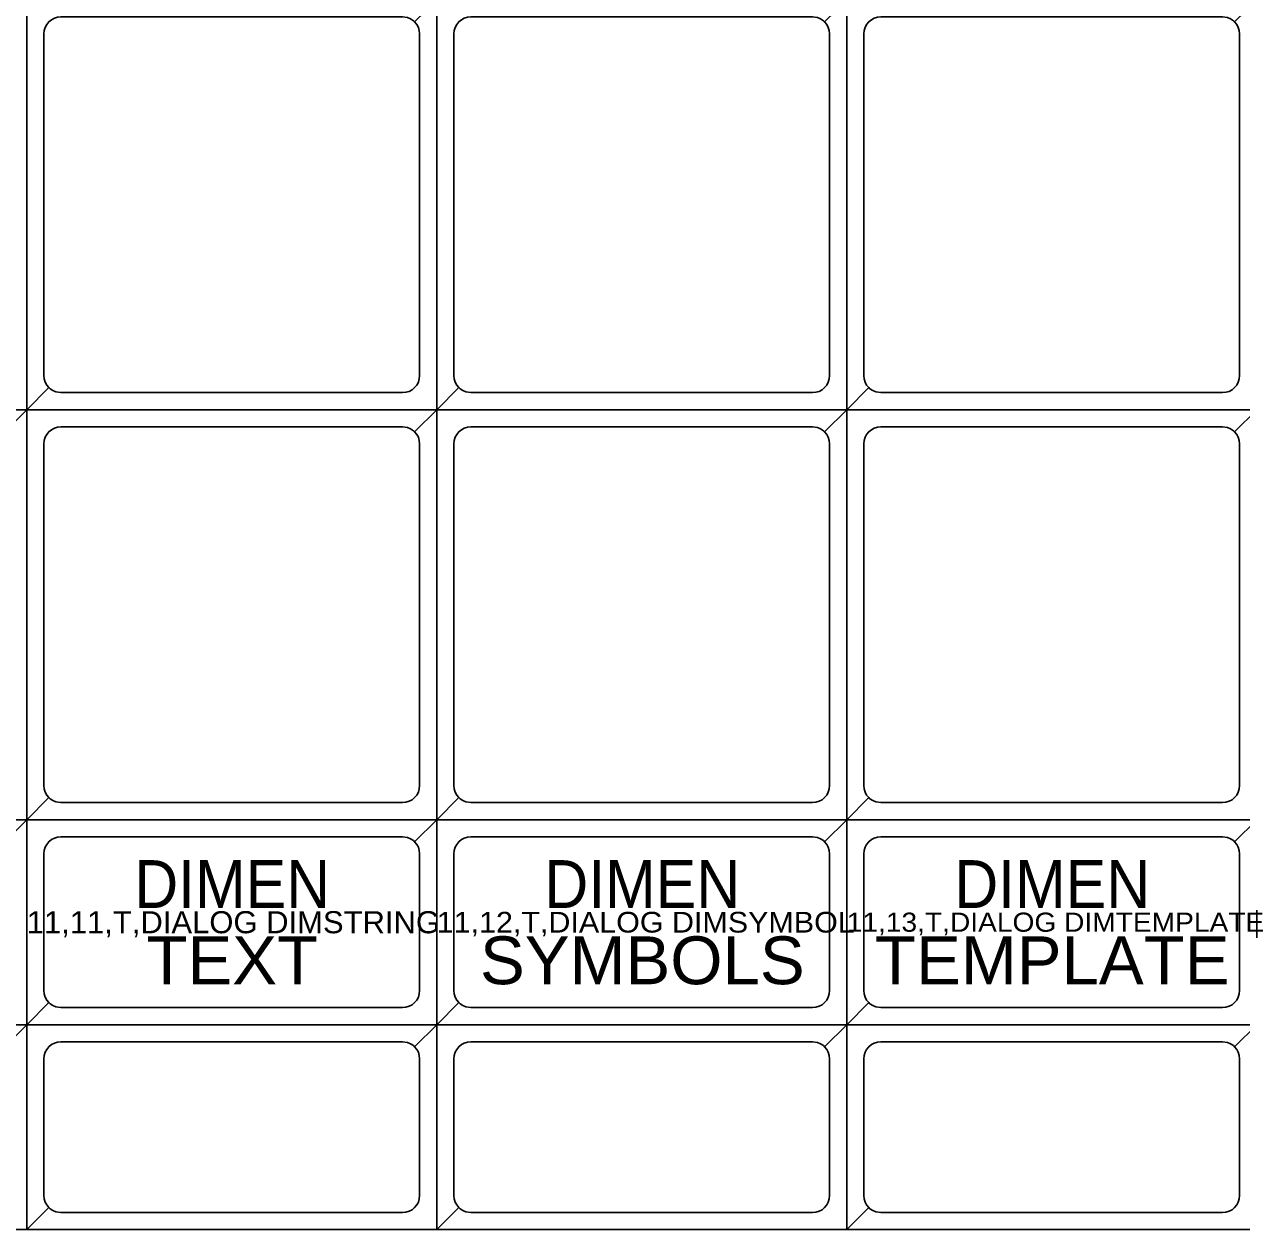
# Model space of a CAD drawing. Extents: x 67896 to 67908, y 49158.5 to 49162.6.
# Drawn here: x 67902.285 to 67904.067, y 49159.033 to 49160.797 of the extents above; entities that cross this region are included whole.
import ezdxf
from ezdxf.enums import TextEntityAlignment as Align

# ---------------------------------------------------------------- set-up
doc = ezdxf.new("R2010")
doc.units = 0
doc.header["$LTSCALE"] = 0.02
for name, color, linetype, lineweight in [('1', 7, 'Continuous', 25), ('2', 7, 'Continuous', 25), ('3', 7, 'Continuous', 25), ('4', 7, 'Continuous', 25), ('5', 7, 'Continuous', 25)]:
    doc.layers.add(name, color=color, linetype=linetype, lineweight=lineweight)
doc.layers.add('63', color=7, linetype='Continuous')

msp = doc.modelspace()

# ---------------------------------------------------------------- linework, layer by layer
at = {"layer": '1'}
for points in [[(67901.6889, 49160.2331), (67902.2889, 49160.2331), (67902.2889, 49160.8331), (67901.6889, 49160.8331)], [(67902.2889, 49160.2331), (67902.8889, 49160.2331), (67902.8889, 49160.8331), (67902.2889, 49160.8331)], [(67902.8889, 49160.2331), (67903.4889, 49160.2331), (67903.4889, 49160.8331), (67902.8889, 49160.8331)], [(67903.4889, 49160.2331), (67904.0889, 49160.2331), (67904.0889, 49160.8331), (67903.4889, 49160.8331)], [(67901.6889, 49159.6331), (67902.2889, 49159.6331), (67902.2889, 49160.2331), (67901.6889, 49160.2331)], [(67902.2889, 49159.6331), (67902.8889, 49159.6331), (67902.8889, 49160.2331), (67902.2889, 49160.2331)], [(67902.8889, 49159.6331), (67903.4889, 49159.6331), (67903.4889, 49160.2331), (67902.8889, 49160.2331)], [(67903.4889, 49159.6331), (67904.0889, 49159.6331), (67904.0889, 49160.2331), (67903.4889, 49160.2331)], [(67901.6889, 49159.3331), (67902.2889, 49159.3331), (67902.2889, 49159.6331), (67901.6889, 49159.6331)], [(67902.2889, 49159.3331), (67902.8889, 49159.3331), (67902.8889, 49159.6331), (67902.2889, 49159.6331)], [(67902.8889, 49159.3331), (67903.4889, 49159.3331), (67903.4889, 49159.6331), (67902.8889, 49159.6331)], [(67903.4889, 49159.3331), (67904.0889, 49159.3331), (67904.0889, 49159.6331), (67903.4889, 49159.6331)], [(67901.6889, 49159.0331), (67902.2889, 49159.0331), (67902.2889, 49159.3331), (67901.6889, 49159.3331)], [(67902.2889, 49159.0331), (67902.8889, 49159.0331), (67902.8889, 49159.3331), (67902.2889, 49159.3331)], [(67902.8889, 49159.0331), (67903.4889, 49159.0331), (67903.4889, 49159.3331), (67902.8889, 49159.3331)], [(67903.4889, 49159.0331), (67904.0889, 49159.0331), (67904.0889, 49159.3331), (67903.4889, 49159.3331)]]:
    msp.add_lwpolyline(points, close=True, dxfattribs=at)
at = {"layer": '2'}
for points in [[(67907.9889, 49159.0331), (67895.9889, 49159.0331), (67895.9889, 49162.6331), (67907.9889, 49162.6331)], [(67901.6889, 49160.2331), (67902.2889, 49160.2331), (67902.2889, 49160.8331), (67901.6889, 49160.8331)], [(67902.2889, 49160.2331), (67902.8889, 49160.2331), (67902.8889, 49160.8331), (67902.2889, 49160.8331)], [(67902.8889, 49160.2331), (67903.4889, 49160.2331), (67903.4889, 49160.8331), (67902.8889, 49160.8331)], [(67903.4889, 49160.2331), (67904.0889, 49160.2331), (67904.0889, 49160.8331), (67903.4889, 49160.8331)], [(67901.6889, 49159.6331), (67902.2889, 49159.6331), (67902.2889, 49160.2331), (67901.6889, 49160.2331)], [(67902.2889, 49159.6331), (67902.8889, 49159.6331), (67902.8889, 49160.2331), (67902.2889, 49160.2331)], [(67902.8889, 49159.6331), (67903.4889, 49159.6331), (67903.4889, 49160.2331), (67902.8889, 49160.2331)], [(67903.4889, 49159.6331), (67904.0889, 49159.6331), (67904.0889, 49160.2331), (67903.4889, 49160.2331)], [(67901.6889, 49159.3331), (67902.2889, 49159.3331), (67902.2889, 49159.6331), (67901.6889, 49159.6331)], [(67902.2889, 49159.3331), (67902.8889, 49159.3331), (67902.8889, 49159.6331), (67902.2889, 49159.6331)], [(67902.8889, 49159.3331), (67903.4889, 49159.3331), (67903.4889, 49159.6331), (67902.8889, 49159.6331)], [(67903.4889, 49159.3331), (67904.0889, 49159.3331), (67904.0889, 49159.6331), (67903.4889, 49159.6331)], [(67901.6889, 49159.0331), (67902.2889, 49159.0331), (67902.2889, 49159.3331), (67901.6889, 49159.3331)], [(67902.2889, 49159.0331), (67902.8889, 49159.0331), (67902.8889, 49159.3331), (67902.2889, 49159.3331)], [(67902.8889, 49159.0331), (67903.4889, 49159.0331), (67903.4889, 49159.3331), (67902.8889, 49159.3331)], [(67903.4889, 49159.0331), (67904.0889, 49159.0331), (67904.0889, 49159.3331), (67903.4889, 49159.3331)]]:
    msp.add_lwpolyline(points, close=True, dxfattribs=at)
at = {"layer": '3'}
for points in [[(67902.8889, 49160.8331), (67902.2889, 49160.8331), (67902.2889, 49160.2331), (67902.3212, 49160.2654), (67902.3181, 49160.2692), (67902.3158, 49160.2735), (67902.3144, 49160.2782), (67902.3139, 49160.2831), (67902.3139, 49160.7831), (67902.3144, 49160.788), (67902.3158, 49160.7927), (67902.3181, 49160.797), (67902.3212, 49160.8008), (67902.3212, 49160.8008), (67902.325, 49160.8039), (67902.3293, 49160.8062), (67902.334, 49160.8076), (67902.3389, 49160.8081), (67902.8389, 49160.8081), (67902.8462, 49160.807), (67902.8507, 49160.8051), (67902.8548, 49160.8024), (67902.8566, 49160.8008)], [(67903.4889, 49160.8331), (67902.8889, 49160.8331), (67902.8889, 49160.2331), (67902.9212, 49160.2654), (67902.9181, 49160.2692), (67902.9158, 49160.2735), (67902.9144, 49160.2782), (67902.9139, 49160.2831), (67902.9139, 49160.7831), (67902.9144, 49160.788), (67902.9158, 49160.7927), (67902.9181, 49160.797), (67902.9212, 49160.8008), (67902.9212, 49160.8008), (67902.925, 49160.8039), (67902.9293, 49160.8062), (67902.934, 49160.8076), (67902.9389, 49160.8081), (67903.4389, 49160.8081), (67903.4462, 49160.807), (67903.4507, 49160.8051), (67903.4548, 49160.8024), (67903.4566, 49160.8008)], [(67904.0889, 49160.8331), (67903.4889, 49160.8331), (67903.4889, 49160.2331), (67903.5212, 49160.2654), (67903.5181, 49160.2692), (67903.5158, 49160.2735), (67903.5144, 49160.2782), (67903.5139, 49160.2831), (67903.5139, 49160.7831), (67903.5144, 49160.788), (67903.5158, 49160.7927), (67903.5181, 49160.797), (67903.5212, 49160.8008), (67903.5212, 49160.8008), (67903.525, 49160.8039), (67903.5293, 49160.8062), (67903.534, 49160.8076), (67903.5389, 49160.8081), (67904.0389, 49160.8081), (67904.0462, 49160.807), (67904.0507, 49160.8051), (67904.0548, 49160.8024), (67904.0566, 49160.8008)], [(67902.2889, 49160.2331), (67901.6889, 49160.2331), (67901.6889, 49159.6331), (67901.7212, 49159.6654), (67901.7181, 49159.6692), (67901.7158, 49159.6735), (67901.7144, 49159.6782), (67901.7139, 49159.6831), (67901.7139, 49160.1831), (67901.7144, 49160.188), (67901.7158, 49160.1927), (67901.7181, 49160.197), (67901.7212, 49160.2008), (67901.7212, 49160.2008), (67901.725, 49160.2039), (67901.7293, 49160.2062), (67901.734, 49160.2076), (67901.7389, 49160.2081), (67902.2389, 49160.2081), (67902.2462, 49160.207), (67902.2507, 49160.2051), (67902.2548, 49160.2024), (67902.2566, 49160.2008)], [(67902.8889, 49160.2331), (67902.2889, 49160.2331), (67902.2889, 49159.6331), (67902.3212, 49159.6654), (67902.3181, 49159.6692), (67902.3158, 49159.6735), (67902.3144, 49159.6782), (67902.3139, 49159.6831), (67902.3139, 49160.1831), (67902.3144, 49160.188), (67902.3158, 49160.1927), (67902.3181, 49160.197), (67902.3212, 49160.2008), (67902.3212, 49160.2008), (67902.325, 49160.2039), (67902.3293, 49160.2062), (67902.334, 49160.2076), (67902.3389, 49160.2081), (67902.8389, 49160.2081), (67902.8462, 49160.207), (67902.8507, 49160.2051), (67902.8548, 49160.2024), (67902.8566, 49160.2008)], [(67903.4889, 49160.2331), (67902.8889, 49160.2331), (67902.8889, 49159.6331), (67902.9212, 49159.6654), (67902.9181, 49159.6692), (67902.9158, 49159.6735), (67902.9144, 49159.6782), (67902.9139, 49159.6831), (67902.9139, 49160.1831), (67902.9144, 49160.188), (67902.9158, 49160.1927), (67902.9181, 49160.197), (67902.9212, 49160.2008), (67902.9212, 49160.2008), (67902.925, 49160.2039), (67902.9293, 49160.2062), (67902.934, 49160.2076), (67902.9389, 49160.2081), (67903.4389, 49160.2081), (67903.4462, 49160.207), (67903.4507, 49160.2051), (67903.4548, 49160.2024), (67903.4566, 49160.2008)], [(67904.0889, 49160.2331), (67903.4889, 49160.2331), (67903.4889, 49159.6331), (67903.5212, 49159.6654), (67903.5181, 49159.6692), (67903.5158, 49159.6735), (67903.5144, 49159.6782), (67903.5139, 49159.6831), (67903.5139, 49160.1831), (67903.5144, 49160.188), (67903.5158, 49160.1927), (67903.5181, 49160.197), (67903.5212, 49160.2008), (67903.5212, 49160.2008), (67903.525, 49160.2039), (67903.5293, 49160.2062), (67903.534, 49160.2076), (67903.5389, 49160.2081), (67904.0389, 49160.2081), (67904.0462, 49160.207), (67904.0507, 49160.2051), (67904.0548, 49160.2024), (67904.0566, 49160.2008)], [(67902.2889, 49159.6331), (67901.6889, 49159.6331), (67901.6889, 49159.3331), (67901.7212, 49159.3654), (67901.7181, 49159.3692), (67901.7158, 49159.3735), (67901.7144, 49159.3782), (67901.7139, 49159.3831), (67901.7139, 49159.5831), (67901.7144, 49159.588), (67901.7158, 49159.5927), (67901.7181, 49159.597), (67901.7212, 49159.6008), (67901.7212, 49159.6008), (67901.725, 49159.6039), (67901.7293, 49159.6062), (67901.734, 49159.6076), (67901.7389, 49159.6081), (67902.2389, 49159.6081), (67902.2462, 49159.607), (67902.2507, 49159.6051), (67902.2548, 49159.6024), (67902.2566, 49159.6008)], [(67902.8889, 49159.6331), (67902.2889, 49159.6331), (67902.2889, 49159.3331), (67902.3212, 49159.3654), (67902.3181, 49159.3692), (67902.3158, 49159.3735), (67902.3144, 49159.3782), (67902.3139, 49159.3831), (67902.3139, 49159.5831), (67902.3144, 49159.588), (67902.3158, 49159.5927), (67902.3181, 49159.597), (67902.3212, 49159.6008), (67902.3212, 49159.6008), (67902.325, 49159.6039), (67902.3293, 49159.6062), (67902.334, 49159.6076), (67902.3389, 49159.6081), (67902.8389, 49159.6081), (67902.8462, 49159.607), (67902.8507, 49159.6051), (67902.8548, 49159.6024), (67902.8566, 49159.6008)], [(67903.4889, 49159.6331), (67902.8889, 49159.6331), (67902.8889, 49159.3331), (67902.9212, 49159.3654), (67902.9181, 49159.3692), (67902.9158, 49159.3735), (67902.9144, 49159.3782), (67902.9139, 49159.3831), (67902.9139, 49159.5831), (67902.9144, 49159.588), (67902.9158, 49159.5927), (67902.9181, 49159.597), (67902.9212, 49159.6008), (67902.9212, 49159.6008), (67902.925, 49159.6039), (67902.9293, 49159.6062), (67902.934, 49159.6076), (67902.9389, 49159.6081), (67903.4389, 49159.6081), (67903.4462, 49159.607), (67903.4507, 49159.6051), (67903.4548, 49159.6024), (67903.4566, 49159.6008)], [(67904.0889, 49159.6331), (67903.4889, 49159.6331), (67903.4889, 49159.3331), (67903.5212, 49159.3654), (67903.5181, 49159.3692), (67903.5158, 49159.3735), (67903.5144, 49159.3782), (67903.5139, 49159.3831), (67903.5139, 49159.5831), (67903.5144, 49159.588), (67903.5158, 49159.5927), (67903.5181, 49159.597), (67903.5212, 49159.6008), (67903.5212, 49159.6008), (67903.525, 49159.6039), (67903.5293, 49159.6062), (67903.534, 49159.6076), (67903.5389, 49159.6081), (67904.0389, 49159.6081), (67904.0462, 49159.607), (67904.0507, 49159.6051), (67904.0548, 49159.6024), (67904.0566, 49159.6008)], [(67902.2889, 49159.3331), (67901.6889, 49159.3331), (67901.6889, 49159.0331), (67901.7212, 49159.0654), (67901.7181, 49159.0692), (67901.7158, 49159.0735), (67901.7144, 49159.0782), (67901.7139, 49159.0831), (67901.7139, 49159.2831), (67901.7144, 49159.288), (67901.7158, 49159.2927), (67901.7181, 49159.297), (67901.7212, 49159.3008), (67901.7212, 49159.3008), (67901.725, 49159.3039), (67901.7293, 49159.3062), (67901.734, 49159.3076), (67901.7389, 49159.3081), (67902.2389, 49159.3081), (67902.2462, 49159.307), (67902.2507, 49159.3051), (67902.2548, 49159.3024), (67902.2566, 49159.3008)], [(67902.8889, 49159.3331), (67902.2889, 49159.3331), (67902.2889, 49159.0331), (67902.3212, 49159.0654), (67902.3181, 49159.0692), (67902.3158, 49159.0735), (67902.3144, 49159.0782), (67902.3139, 49159.0831), (67902.3139, 49159.2831), (67902.3144, 49159.288), (67902.3158, 49159.2927), (67902.3181, 49159.297), (67902.3212, 49159.3008), (67902.3212, 49159.3008), (67902.325, 49159.3039), (67902.3293, 49159.3062), (67902.334, 49159.3076), (67902.3389, 49159.3081), (67902.8389, 49159.3081), (67902.8462, 49159.307), (67902.8507, 49159.3051), (67902.8548, 49159.3024), (67902.8566, 49159.3008)], [(67903.4889, 49159.3331), (67902.8889, 49159.3331), (67902.8889, 49159.0331), (67902.9212, 49159.0654), (67902.9181, 49159.0692), (67902.9158, 49159.0735), (67902.9144, 49159.0782), (67902.9139, 49159.0831), (67902.9139, 49159.2831), (67902.9144, 49159.288), (67902.9158, 49159.2927), (67902.9181, 49159.297), (67902.9212, 49159.3008), (67902.9212, 49159.3008), (67902.925, 49159.3039), (67902.9293, 49159.3062), (67902.934, 49159.3076), (67902.9389, 49159.3081), (67903.4389, 49159.3081), (67903.4462, 49159.307), (67903.4507, 49159.3051), (67903.4548, 49159.3024), (67903.4566, 49159.3008)], [(67904.0889, 49159.3331), (67903.4889, 49159.3331), (67903.4889, 49159.0331), (67903.5212, 49159.0654), (67903.5181, 49159.0692), (67903.5158, 49159.0735), (67903.5144, 49159.0782), (67903.5139, 49159.0831), (67903.5139, 49159.2831), (67903.5144, 49159.288), (67903.5158, 49159.2927), (67903.5181, 49159.297), (67903.5212, 49159.3008), (67903.5212, 49159.3008), (67903.525, 49159.3039), (67903.5293, 49159.3062), (67903.534, 49159.3076), (67903.5389, 49159.3081), (67904.0389, 49159.3081), (67904.0462, 49159.307), (67904.0507, 49159.3051), (67904.0548, 49159.3024), (67904.0566, 49159.3008)]]:
    msp.add_lwpolyline(points, close=True, dxfattribs=at)
at = {"layer": '4'}
for points in [[(67901.6889, 49160.2331), (67902.2889, 49160.2331), (67902.2889, 49160.8331), (67902.2566, 49160.8008), (67902.2597, 49160.797), (67902.262, 49160.7927), (67902.2634, 49160.788), (67902.2639, 49160.7831), (67902.2639, 49160.2831), (67902.2634, 49160.2782), (67902.262, 49160.2735), (67902.2597, 49160.2692), (67902.2566, 49160.2654), (67902.2566, 49160.2654), (67902.2528, 49160.2623), (67902.2485, 49160.26), (67902.2438, 49160.2586), (67902.2389, 49160.2581), (67901.7389, 49160.2581), (67901.7316, 49160.2592), (67901.7271, 49160.2611), (67901.723, 49160.2638), (67901.7212, 49160.2654)], [(67902.2889, 49160.2331), (67902.8889, 49160.2331), (67902.8889, 49160.8331), (67902.8566, 49160.8008), (67902.8597, 49160.797), (67902.862, 49160.7927), (67902.8634, 49160.788), (67902.8639, 49160.7831), (67902.8639, 49160.2831), (67902.8634, 49160.2782), (67902.862, 49160.2735), (67902.8597, 49160.2692), (67902.8566, 49160.2654), (67902.8566, 49160.2654), (67902.8528, 49160.2623), (67902.8485, 49160.26), (67902.8438, 49160.2586), (67902.8389, 49160.2581), (67902.3389, 49160.2581), (67902.3316, 49160.2592), (67902.3271, 49160.2611), (67902.323, 49160.2638), (67902.3212, 49160.2654)], [(67902.8889, 49160.2331), (67903.4889, 49160.2331), (67903.4889, 49160.8331), (67903.4566, 49160.8008), (67903.4597, 49160.797), (67903.462, 49160.7927), (67903.4634, 49160.788), (67903.4639, 49160.7831), (67903.4639, 49160.2831), (67903.4634, 49160.2782), (67903.462, 49160.2735), (67903.4597, 49160.2692), (67903.4566, 49160.2654), (67903.4566, 49160.2654), (67903.4528, 49160.2623), (67903.4485, 49160.26), (67903.4438, 49160.2586), (67903.4389, 49160.2581), (67902.9389, 49160.2581), (67902.9316, 49160.2592), (67902.9271, 49160.2611), (67902.923, 49160.2638), (67902.9212, 49160.2654)], [(67903.4889, 49160.2331), (67904.0889, 49160.2331), (67904.0889, 49160.8331), (67904.0566, 49160.8008), (67904.0597, 49160.797), (67904.062, 49160.7927), (67904.0634, 49160.788), (67904.0639, 49160.7831), (67904.0639, 49160.2831), (67904.0634, 49160.2782), (67904.062, 49160.2735), (67904.0597, 49160.2692), (67904.0566, 49160.2654), (67904.0566, 49160.2654), (67904.0528, 49160.2623), (67904.0485, 49160.26), (67904.0438, 49160.2586), (67904.0389, 49160.2581), (67903.5389, 49160.2581), (67903.5316, 49160.2592), (67903.5271, 49160.2611), (67903.523, 49160.2638), (67903.5212, 49160.2654)], [(67901.6889, 49159.6331), (67902.2889, 49159.6331), (67902.2889, 49160.2331), (67902.2566, 49160.2008), (67902.2597, 49160.197), (67902.262, 49160.1927), (67902.2634, 49160.188), (67902.2639, 49160.1831), (67902.2639, 49159.6831), (67902.2634, 49159.6782), (67902.262, 49159.6735), (67902.2597, 49159.6692), (67902.2566, 49159.6654), (67902.2566, 49159.6654), (67902.2528, 49159.6623), (67902.2485, 49159.66), (67902.2438, 49159.6586), (67902.2389, 49159.6581), (67901.7389, 49159.6581), (67901.7316, 49159.6592), (67901.7271, 49159.6611), (67901.723, 49159.6638), (67901.7212, 49159.6654)], [(67902.2889, 49159.6331), (67902.8889, 49159.6331), (67902.8889, 49160.2331), (67902.8566, 49160.2008), (67902.8597, 49160.197), (67902.862, 49160.1927), (67902.8634, 49160.188), (67902.8639, 49160.1831), (67902.8639, 49159.6831), (67902.8634, 49159.6782), (67902.862, 49159.6735), (67902.8597, 49159.6692), (67902.8566, 49159.6654), (67902.8566, 49159.6654), (67902.8528, 49159.6623), (67902.8485, 49159.66), (67902.8438, 49159.6586), (67902.8389, 49159.6581), (67902.3389, 49159.6581), (67902.3316, 49159.6592), (67902.3271, 49159.6611), (67902.323, 49159.6638), (67902.3212, 49159.6654)], [(67902.8889, 49159.6331), (67903.4889, 49159.6331), (67903.4889, 49160.2331), (67903.4566, 49160.2008), (67903.4597, 49160.197), (67903.462, 49160.1927), (67903.4634, 49160.188), (67903.4639, 49160.1831), (67903.4639, 49159.6831), (67903.4634, 49159.6782), (67903.462, 49159.6735), (67903.4597, 49159.6692), (67903.4566, 49159.6654), (67903.4566, 49159.6654), (67903.4528, 49159.6623), (67903.4485, 49159.66), (67903.4438, 49159.6586), (67903.4389, 49159.6581), (67902.9389, 49159.6581), (67902.9316, 49159.6592), (67902.9271, 49159.6611), (67902.923, 49159.6638), (67902.9212, 49159.6654)], [(67903.4889, 49159.6331), (67904.0889, 49159.6331), (67904.0889, 49160.2331), (67904.0566, 49160.2008), (67904.0597, 49160.197), (67904.062, 49160.1927), (67904.0634, 49160.188), (67904.0639, 49160.1831), (67904.0639, 49159.6831), (67904.0634, 49159.6782), (67904.062, 49159.6735), (67904.0597, 49159.6692), (67904.0566, 49159.6654), (67904.0566, 49159.6654), (67904.0528, 49159.6623), (67904.0485, 49159.66), (67904.0438, 49159.6586), (67904.0389, 49159.6581), (67903.5389, 49159.6581), (67903.5316, 49159.6592), (67903.5271, 49159.6611), (67903.523, 49159.6638), (67903.5212, 49159.6654)], [(67901.6889, 49159.3331), (67902.2889, 49159.3331), (67902.2889, 49159.6331), (67902.2566, 49159.6008), (67902.2597, 49159.597), (67902.262, 49159.5927), (67902.2634, 49159.588), (67902.2639, 49159.5831), (67902.2639, 49159.3831), (67902.2634, 49159.3782), (67902.262, 49159.3735), (67902.2597, 49159.3692), (67902.2566, 49159.3654), (67902.2566, 49159.3654), (67902.2528, 49159.3623), (67902.2485, 49159.36), (67902.2438, 49159.3586), (67902.2389, 49159.3581), (67901.7389, 49159.3581), (67901.7316, 49159.3592), (67901.7271, 49159.3611), (67901.723, 49159.3638), (67901.7212, 49159.3654)], [(67902.2889, 49159.3331), (67902.8889, 49159.3331), (67902.8889, 49159.6331), (67902.8566, 49159.6008), (67902.8597, 49159.597), (67902.862, 49159.5927), (67902.8634, 49159.588), (67902.8639, 49159.5831), (67902.8639, 49159.3831), (67902.8634, 49159.3782), (67902.862, 49159.3735), (67902.8597, 49159.3692), (67902.8566, 49159.3654), (67902.8566, 49159.3654), (67902.8528, 49159.3623), (67902.8485, 49159.36), (67902.8438, 49159.3586), (67902.8389, 49159.3581), (67902.3389, 49159.3581), (67902.3316, 49159.3592), (67902.3271, 49159.3611), (67902.323, 49159.3638), (67902.3212, 49159.3654)], [(67902.8889, 49159.3331), (67903.4889, 49159.3331), (67903.4889, 49159.6331), (67903.4566, 49159.6008), (67903.4597, 49159.597), (67903.462, 49159.5927), (67903.4634, 49159.588), (67903.4639, 49159.5831), (67903.4639, 49159.3831), (67903.4634, 49159.3782), (67903.462, 49159.3735), (67903.4597, 49159.3692), (67903.4566, 49159.3654), (67903.4566, 49159.3654), (67903.4528, 49159.3623), (67903.4485, 49159.36), (67903.4438, 49159.3586), (67903.4389, 49159.3581), (67902.9389, 49159.3581), (67902.9316, 49159.3592), (67902.9271, 49159.3611), (67902.923, 49159.3638), (67902.9212, 49159.3654)], [(67903.4889, 49159.3331), (67904.0889, 49159.3331), (67904.0889, 49159.6331), (67904.0566, 49159.6008), (67904.0597, 49159.597), (67904.062, 49159.5927), (67904.0634, 49159.588), (67904.0639, 49159.5831), (67904.0639, 49159.3831), (67904.0634, 49159.3782), (67904.062, 49159.3735), (67904.0597, 49159.3692), (67904.0566, 49159.3654), (67904.0566, 49159.3654), (67904.0528, 49159.3623), (67904.0485, 49159.36), (67904.0438, 49159.3586), (67904.0389, 49159.3581), (67903.5389, 49159.3581), (67903.5316, 49159.3592), (67903.5271, 49159.3611), (67903.523, 49159.3638), (67903.5212, 49159.3654)], [(67901.6889, 49159.0331), (67902.2889, 49159.0331), (67902.2889, 49159.3331), (67902.2566, 49159.3008), (67902.2597, 49159.297), (67902.262, 49159.2927), (67902.2634, 49159.288), (67902.2639, 49159.2831), (67902.2639, 49159.0831), (67902.2634, 49159.0782), (67902.262, 49159.0735), (67902.2597, 49159.0692), (67902.2566, 49159.0654), (67902.2566, 49159.0654), (67902.2528, 49159.0623), (67902.2485, 49159.06), (67902.2438, 49159.0586), (67902.2389, 49159.0581), (67901.7389, 49159.0581), (67901.7316, 49159.0592), (67901.7271, 49159.0611), (67901.723, 49159.0638), (67901.7212, 49159.0654)], [(67902.2889, 49159.0331), (67902.8889, 49159.0331), (67902.8889, 49159.3331), (67902.8566, 49159.3008), (67902.8597, 49159.297), (67902.862, 49159.2927), (67902.8634, 49159.288), (67902.8639, 49159.2831), (67902.8639, 49159.0831), (67902.8634, 49159.0782), (67902.862, 49159.0735), (67902.8597, 49159.0692), (67902.8566, 49159.0654), (67902.8566, 49159.0654), (67902.8528, 49159.0623), (67902.8485, 49159.06), (67902.8438, 49159.0586), (67902.8389, 49159.0581), (67902.3389, 49159.0581), (67902.3316, 49159.0592), (67902.3271, 49159.0611), (67902.323, 49159.0638), (67902.3212, 49159.0654)], [(67902.8889, 49159.0331), (67903.4889, 49159.0331), (67903.4889, 49159.3331), (67903.4566, 49159.3008), (67903.4597, 49159.297), (67903.462, 49159.2927), (67903.4634, 49159.288), (67903.4639, 49159.2831), (67903.4639, 49159.0831), (67903.4634, 49159.0782), (67903.462, 49159.0735), (67903.4597, 49159.0692), (67903.4566, 49159.0654), (67903.4566, 49159.0654), (67903.4528, 49159.0623), (67903.4485, 49159.06), (67903.4438, 49159.0586), (67903.4389, 49159.0581), (67902.9389, 49159.0581), (67902.9316, 49159.0592), (67902.9271, 49159.0611), (67902.923, 49159.0638), (67902.9212, 49159.0654)], [(67903.4889, 49159.0331), (67904.0889, 49159.0331), (67904.0889, 49159.3331), (67904.0566, 49159.3008), (67904.0597, 49159.297), (67904.062, 49159.2927), (67904.0634, 49159.288), (67904.0639, 49159.2831), (67904.0639, 49159.0831), (67904.0634, 49159.0782), (67904.062, 49159.0735), (67904.0597, 49159.0692), (67904.0566, 49159.0654), (67904.0566, 49159.0654), (67904.0528, 49159.0623), (67904.0485, 49159.06), (67904.0438, 49159.0586), (67904.0389, 49159.0581), (67903.5389, 49159.0581), (67903.5316, 49159.0592), (67903.5271, 49159.0611), (67903.523, 49159.0638), (67903.5212, 49159.0654)]]:
    msp.add_lwpolyline(points, close=True, dxfattribs=at)

# ---------------------------------------------------------------- texts
at = {"layer": '5'}
for s, width, p in [('DIMEN', 0.95, (67902.5896, 49159.5039)), ('DIMEN', 0.95, (67903.1897, 49159.5039)), ('DIMEN', 0.95, (67903.7897, 49159.5039)), ('TEXT', 1.05, (67902.5896, 49159.3923)), ('SYMBOLS', 1.05, (67903.1898, 49159.3923)), ('TEMPLATE', 1.05, (67903.7897, 49159.3923))]:
    msp.add_text(s, height=0.07, dxfattribs=dict(at, width=width)).set_placement(p, align=Align.CENTER)
at = {"layer": '63'}
for s, height, width, p in [('11,11,T,DIALOG DIMSTRING', 0.0323, 1.05, (67902.2889, 49159.4669)), ('11,12,T,DIALOG DIMSYMBOL', 0.0303, 1.1, (67902.8889, 49159.4679)), ('11,13,T,DIALOG DIMTEMPLATE', 0.028, 1.1, (67903.4889, 49159.4691))]:
    msp.add_text(s, height=height, dxfattribs=dict(at, width=width)).set_placement(p)

doc.saveas('drawing.dxf')
